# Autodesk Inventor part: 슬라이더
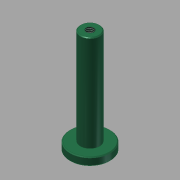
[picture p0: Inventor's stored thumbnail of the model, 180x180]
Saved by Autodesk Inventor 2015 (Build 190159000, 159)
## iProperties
Created: 2016-02
Part Number: 슬라이더
Material: 스테인리스강
Document SubType Name: Modeling
Designer: mduedu
Density: 8.08 g/cm^3
Appearance: 매끄러움 - 짙은 바다 녹색
Mass: 72.5507 g
Surface Area: 37.669 cm^2
Volume: 8.97904 cm^3
Author: mduedu
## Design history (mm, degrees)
sketch "스케치1"
  geometry: C1 r 12.5 at (0, 0); 1 further point
  constraints: 1 centre point, 1 coincident
  dimensions: "d0" = 25 diameter of C1
extrude "돌출1" new body sketch "스케치1" distance "d1" = 5; taper "d2" = 0 deg
sketch "스케치2"
  geometry: C1 r 6 at (0, 0); 1 further point
  constraints: 1 centre point, 1 coincident
  dimensions: "d3" = 12 diameter of C1
extrude "돌출2" join sketch "스케치2" distance "d4" = 60; taper "d5" = 0 deg
chamfer "모따기1" distance "d6" = 0.5; stored, may be unused: second distance "d7" = 2, angle "d8" = 45 deg
hole "구멍1" diameter "d11" = 4.917; stored, may be unused: countersink angle "d15" = 90 deg, drill point angle "d17" = 118 deg; dims "d9" = 10, "d10" = 10, "d12" = 10, "d13" = 4, "d14" = 2, "d16" = 12
chamfer "모따기2" distance "d18" = 0.5; stored, may be unused: second distance "d19" = 2, angle "d20" = 45 deg
node "솔리드1"
